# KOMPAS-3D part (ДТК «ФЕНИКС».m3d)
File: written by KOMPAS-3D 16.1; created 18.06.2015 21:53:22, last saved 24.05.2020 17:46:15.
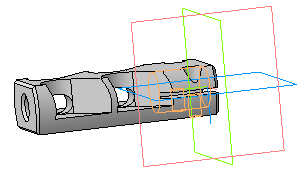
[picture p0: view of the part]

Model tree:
1. Эскиз:1
2. Операция выдавливания:1
     Расстояние 1 = 65
3. Эскиз:2
4. Вырезать элемент выдавливания:4
     Расстояние 1 = 20
5. Фаска:1
     Угол = 45; Длина 1 = 1; Длина 2 = 1
6. Эскиз:5
7. Вырезать элемент выдавливания:5
     Расстояние 1 = 70
8. Эскиз:6
9. Вырезать элемент выдавливания:6
     Расстояние 2 = 3.5; Расстояние 1 = 10
10. Эскиз:7
11. Вырезать элемент выдавливания:7
     Расстояние 2 = 3.5; Расстояние 1 = 60
12. Фаска:2
     Угол = 45; Длина 1 = 1; Длина 2 = 1
13. Фаска:3
     Угол = 45; Длина 1 = 1; Длина 2 = 1
14. Эскиз:8
15. Вырезать элемент выдавливания:8
     Расстояние 2 = 3.5; Расстояние 1 = 6
16. Эскиз:9
17. Вырезать элемент выдавливания:9
     Расстояние 2 = 3.5; Расстояние 1 = 17
18. Эскиз:11
19. Вырезать элемент выдавливания:10
     Расстояние 2 = 3.5; Расстояние 1 = 20
20. Условное изображение резьбы:1
     Длина резьбы = 18; Шаг резьбы = 1; Номинальный диаметр резьбы = 14.0825
21. Условное изображение резьбы:2
     Длина резьбы = 7.5; Шаг резьбы = 0.7; Номинальный диаметр резьбы = 4.05777
22. Условное изображение резьбы:3  (labels: Zebra 000; Сталь 20  ГОСТ 1050-88; SYSTEM_PROPERTY_ADDITIONAL_FOR:20.000000)
     Длина резьбы = 7.5; Шаг резьбы = 1; Номинальный диаметр резьбы = 4.38253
